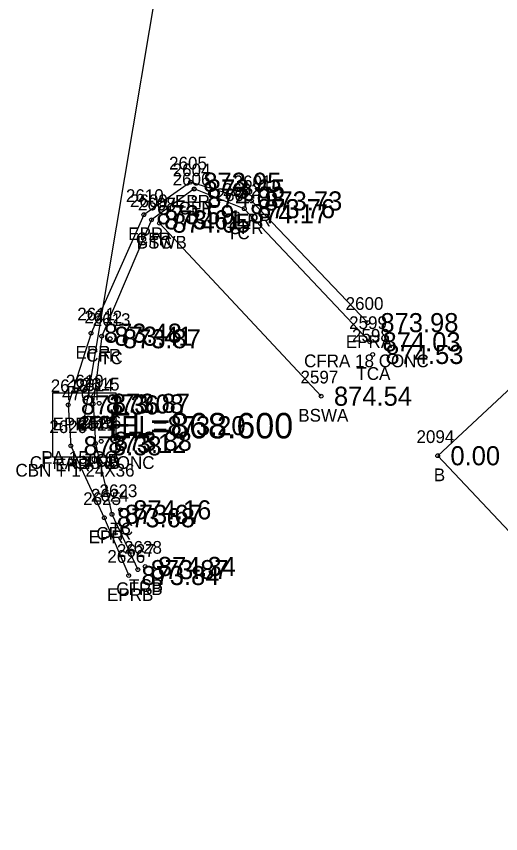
# Model space of a CAD drawing. Extents: x 1622501 to 1626664, y 1117816 to 1121579.
# Drawn here: x 1623759.2 to 1623797.3, y 1118887.8 to 1118952 of the extents above; entities that cross this region are included whole.
import ezdxf

# ---------------------------------------------------------------- set-up
doc = ezdxf.new("R2010")
doc.units = 0
for name, color, linetype in [('RD_EX_Bldg', 7, 'Continuous'), ('RD_EX_Bldg_txCode', 7, 'Continuous'), ('RD_EX_Conc', 7, 'Continuous'), ('RD_EX_Conc_txCode', 7, 'Continuous'), ('RD_EX_DR_Inlet', 7, 'Continuous'), ('RD_EX_DR_Inlet_txCode', 7, 'Continuous'), ('RD_EX_DR_Pipe', 7, 'Continuous'), ('RD_EX_DR_Pipe_txCode', 7, 'Continuous'), ('RD_EX_Road', 7, 'Continuous'), ('RD_EX_Road_txCode', 7, 'Continuous'), ('RD_EX_TX_Bldg_ELEV', 7, 'Continuous'), ('RD_EX_TX_Conc_ELEV', 7, 'Continuous'), ('RD_EX_TX_DR_Inlet_ELEV', 7, 'Continuous'), ('RD_EX_TX_Road_ELEV', 7, 'Continuous'), ('RD_SMD_Locator', 7, 'Continuous'), ('RD_TX_Pipe_ElevEX', 7, 'Continuous')]:
    doc.layers.add(name, color=color, linetype=linetype)

msp = doc.modelspace()

# ---------------------------------------------------------------- linework, layer by layer
at = {"layer": 'RD_EX_Bldg'}
msp.add_lwpolyline([(1623894.311, 1119012.492), (1623792.359, 1118917.49), (1623836.571, 1118870.621), (1623938.523, 1118965.623), (1623894.311, 1119012.492)], dxfattribs=at)
at = {"layer": 'RD_EX_Conc'}
msp.add_line((1623783.199, 1118922.168), (1623770.48, 1118935.767), dxfattribs=at)
msp.add_lwpolyline([(1623787.022, 1118926.444), (1623777.153, 1118936.902), (1623773.211, 1118938.448), (1623769.856, 1118936.027), (1623765.943, 1118926.883), (1623765.263, 1118921.558), (1623765.458, 1118918.453), (1623765.458, 1118918.453), (1623766.747, 1118912.889), (1623768.785, 1118908.544)], dxfattribs=at)
at = {"layer": 'RD_EX_DR_Inlet'}
msp.add_line((1623767.082, 1118917.398), (1623767.082, 1118922.398), dxfattribs=at)
msp.add_lwpolyline([(1623767.082, 1118917.398), (1623767.082, 1118922.398), (1623762.082, 1118922.398), (1623762.082, 1118917.398)], close=True, dxfattribs=at)
at = {"layer": 'RD_EX_DR_Pipe'}
msp.add_lwpolyline([(1623764.491, 1118919.853), (1623773.64, 1118974.335), (1623825.837, 1119022.936), (1623907.44, 1119083.04), (1623936.884, 1119056.765)], dxfattribs=at)
at = {"layer": 'RD_EX_Road'}
msp.add_lwpolyline([(1623786.851, 1118927.948), (1623777.721, 1118937.511), (1623772.93, 1118938.979), (1623769.25, 1118936.428), (1623765.105, 1118927.12), (1623763.303, 1118921.483), (1623763.512, 1118918.273), (1623766.14, 1118912.618), (1623768.062, 1118908.081)], dxfattribs=at)
at = {"layer": 'RD_SMD_Locator'}
for centre, radius in [((1623772.93, 1118938.979), 0.15), ((1623773.211, 1118938.448), 0.15), ((1623773.23, 1118937.723), 0.15), ((1623777.721, 1118937.511), 0.15), ((1623769.25, 1118936.428), 0.15), ((1623776.593, 1118936.501), 0.15), ((1623777.153, 1118936.902), 0.15), ((1623769.856, 1118936.027), 0.15), ((1623770.48, 1118935.767), 0.15), ((1623770.48, 1118935.767), 0.15), ((1623786.851, 1118927.948), 0.15), ((1623765.105, 1118927.12), 0.15), ((1623765.943, 1118926.883), 0.15), ((1623766.601, 1118926.684), 0.15), ((1623787.022, 1118926.444), 0.15), ((1623787.249, 1118925.45), 0.15), ((1623783.199, 1118922.168), 0.15), ((1623765.263, 1118921.558), 0.15), ((1623765.74, 1118921.613), 0.15), ((1623763.303, 1118921.483), 0.15), ((1623764.491, 1118919.853), 0.2), ((1623764.491, 1118919.853), 0.15), ((1623765.458, 1118918.453), 0.15), ((1623765.458, 1118918.453), 0.15), ((1623765.894, 1118918.626), 0.15), ((1623765.894, 1118918.626), 0.15), ((1623763.512, 1118918.273), 0.15), ((1623792.359, 1118917.49), 0.15), ((1623767.422, 1118913.239), 0.15), ((1623766.14, 1118912.618), 0.15), ((1623766.747, 1118912.889), 0.15), ((1623769.354, 1118908.792), 0.15), ((1623768.062, 1118908.081), 0.15), ((1623768.785, 1118908.544), 0.15)]:
    msp.add_circle(centre, radius, dxfattribs=at)

# ---------------------------------------------------------------- texts
at = {"layer": 'RD_EX_Bldg_txCode'}
for s, p in [('2094', (1623790.69, 1118918.49)), ('B', (1623792.052, 1118915.49))]:
    msp.add_text(s, height=1, dxfattribs=at).set_placement(p)
at = {"layer": 'RD_EX_Conc_txCode'}
for s, p in [('2604', (1623771.518, 1118939.448)), ('2606', (1623771.513, 1118938.723)), ('2603', (1623774.9, 1118937.501)), ('2602', (1623775.46, 1118937.902)), ('2609', (1623768.163, 1118937.027)), ('2607', (1623768.787, 1118936.767)), ('2608', (1623768.787, 1118936.767)), ('CFR', (1623771.983, 1118936.448)), ('TC', (1623772.434, 1118935.723)), ('CFR', (1623775.924, 1118934.902)), ('TC', (1623775.798, 1118934.501)), ('CFR', (1623768.627, 1118934.027)), ('BSWB', (1623768.692, 1118933.767)), ('TC', (1623769.684, 1118933.767)), ('2612', (1623764.573, 1118927.883)), ('2613', (1623765.231, 1118927.684)), ('2599', (1623785.392, 1118927.444)), ('2598', (1623785.619, 1118926.45)), ('CFR', (1623764.715, 1118924.883)), ('TC', (1623765.806, 1118924.684)), ('CFRA 18 CONC', (1623781.849, 1118924.444)), ('TCA', (1623785.965, 1118923.45)), ('2615', (1623764.37, 1118922.613)), ('2597', (1623781.569, 1118923.168)), ('2614', (1623763.893, 1118922.558)), ('BSWA', (1623781.396, 1118920.168)), ('CFR', (1623764.034, 1118919.558)), ('2617', (1623764.088, 1118919.453)), ('2621', (1623764.088, 1118919.453)), ('2622', (1623764.241, 1118919.626)), ('2616', (1623764.5, 1118919.626)), ('TC', (1623764.944, 1118919.613)), ('CFRA 18 CONC', (1623760.285, 1118916.453)), ('CFRB', (1623763.757, 1118916.453)), ('TCA', (1623764.611, 1118916.626)), ('TCB', (1623764.626, 1118916.626)), ('2623', (1623765.768, 1118914.239)), ('2624', (1623765.094, 1118913.889)), ('TC', (1623766.626, 1118911.239)), ('CFR', (1623765.519, 1118910.889)), ('2628', (1623767.701, 1118909.792)), ('2627', (1623767.131, 1118909.544)), ('CFRB', (1623767.084, 1118906.544)), ('TCB', (1623768.087, 1118906.792))]:
    msp.add_text(s, height=1, dxfattribs=at).set_placement(p)
at = {"layer": 'RD_EX_DR_Inlet_txCode'}
for s, p in [('2619', (1623763.121, 1118922.853)), ('CBN T 1 24X36', (1623759.16, 1118915.853))]:
    msp.add_text(s, height=1, dxfattribs=at).set_placement(p)
at = {"layer": 'RD_EX_DR_Pipe_txCode'}
for s, p in [('4704', (1623762.822, 1118921.853)), ('PA 15 RC', (1623761.2, 1118916.853))]:
    msp.add_text(s, height=1, dxfattribs=at).set_placement(p)
at = {"layer": 'RD_EX_Road_txCode'}
for s, p in [('2605', (1623771.237, 1118939.979)), ('2601', (1623776.311, 1118938.511)), ('2610', (1623767.841, 1118937.428)), ('EPR', (1623771.702, 1118936.979)), ('EPR', (1623776.492, 1118935.511)), ('EPR', (1623768.022, 1118934.428)), ('2600', (1623785.118, 1118928.948)), ('2611', (1623764.018, 1118928.12)), ('EPRA', (1623785.134, 1118925.948)), ('EPR', (1623763.876, 1118925.12)), ('2618', (1623761.933, 1118922.483)), ('EPR', (1623762.075, 1118919.483)), ('2620', (1623761.819, 1118919.273)), ('EPR', (1623762.283, 1118916.273)), ('2625', (1623764.486, 1118913.618)), ('EPR', (1623764.911, 1118910.618)), ('2626', (1623766.385, 1118909.081)), ('EPRB', (1623766.361, 1118906.081))]:
    msp.add_text(s, height=1, dxfattribs=at).set_placement(p)
at = {"layer": 'RD_EX_TX_Bldg_ELEV'}
msp.add_text('0.00', height=1.5, dxfattribs=at).set_placement((1623793.359, 1118916.74))
at = {"layer": 'RD_EX_TX_Conc_ELEV'}
for s, p in [('873.65', (1623774.211, 1118937.698)), ('874.08', (1623774.23, 1118936.973)), ('874.17', (1623777.593, 1118935.751)), ('873.76', (1623778.153, 1118936.152)), ('873.61', (1623770.856, 1118935.277)), ('874.05', (1623771.48, 1118935.017)), ('874.05', (1623771.48, 1118935.017)), ('873.41', (1623766.943, 1118926.133)), ('873.87', (1623767.601, 1118925.934)), ('874.03', (1623788.022, 1118925.694)), ('874.53', (1623788.249, 1118924.7)), ('874.54', (1623784.199, 1118921.418)), ('873.08', (1623766.263, 1118920.808)), ('873.87', (1623766.74, 1118920.863)), ('873.12', (1623766.458, 1118917.703)), ('873.12', (1623766.458, 1118917.703)), ('873.88', (1623766.894, 1118917.876)), ('873.88', (1623766.894, 1118917.876)), ('874.16', (1623768.422, 1118912.489)), ('873.67', (1623767.747, 1118912.139)), ('874.34', (1623770.354, 1118908.042)), ('873.87', (1623769.785, 1118907.794))]:
    msp.add_text(s, height=1.5, dxfattribs=at).set_placement(p)
at = {"layer": 'RD_EX_TX_DR_Inlet_ELEV'}
msp.add_text('EL=873.20', height=1.5, dxfattribs=at).set_placement((1623767.491, 1118919.103))
at = {"layer": 'RD_EX_TX_Road_ELEV'}
for s, p in [('873.95', (1623773.93, 1118938.229)), ('873.73', (1623778.721, 1118936.761)), ('873.59', (1623770.25, 1118935.678)), ('873.98', (1623787.851, 1118927.198)), ('873.48', (1623766.105, 1118926.37)), ('873.36', (1623764.303, 1118920.733)), ('873.38', (1623764.512, 1118917.523)), ('873.68', (1623767.14, 1118911.868)), ('873.84', (1623769.062, 1118907.331))]:
    msp.add_text(s, height=1.5, dxfattribs=at).set_placement(p)
at = {"layer": 'RD_TX_Pipe_ElevEX'}
msp.add_text('EL=868.600', height=2, dxfattribs=at).set_placement((1623766.491, 1118918.853))

doc.saveas('drawing.dxf')
